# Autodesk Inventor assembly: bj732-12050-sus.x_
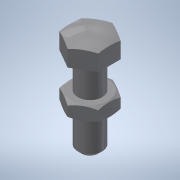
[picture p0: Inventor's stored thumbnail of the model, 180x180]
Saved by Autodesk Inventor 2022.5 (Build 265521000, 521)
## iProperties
Created: 2019-10
Part Number: bj732-12050-sus.x_
Material: 一般
Document SubType Name: Assembly
Designer: ImaoCorp
Sending System: SOLIDWORKS 2017-2017317
MC: AMD64
MC_MODEL: Intel64 Family 6 Model 60 Stepping 3, GenuineIntel
OS: Windows_NT
FRU: Parasolid Version 29.0, build 201,  4-17-2017
FORMAT: text
GUISE: transmit
KEY: bj732-12050-sus
FILE: bj732-12050-sus.x_t
DATE: Wed Oct 30 16:05:16 2019
Author: ImaoCorp
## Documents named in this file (3)
- X:\14_SW2022-Inv2022\00_全2023-1023新製品(TCC)まで\b\bj732-12050-sus\BJ732-12050-SUS.iam
- X:\14_SW2022-Inv2022\00_全2023-1023新製品(TCC)まで\b\bj732-12050-sus\bj732-12050-sus_01.ipt
- X:\14_SW2022-Inv2022\00_全2023-1023新製品(TCC)まで\b\bj732-12050-sus\bj732-12050-sus_02.ipt
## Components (2 placed, 2 different names)
1. bj732-12050-sus_01
2. bj732-12050-sus_02
